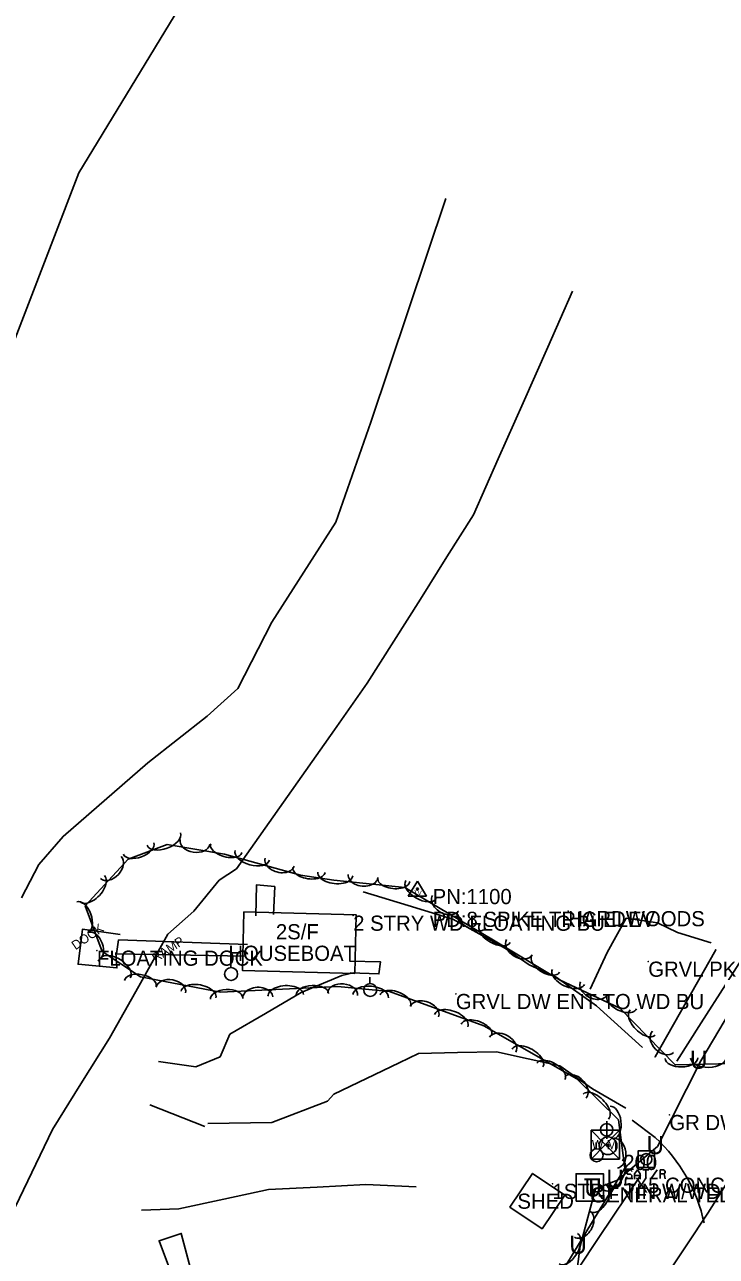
# Model space of a CAD drawing. Extents: x 1451369 to 1458940, y 1868647 to 1875095.
# Drawn here: x 1454865 to 1455092.6, y 1872324.4 to 1872730.1 of the extents above; entities that cross this region are included whole.
import ezdxf

# ---------------------------------------------------------------- set-up
doc = ezdxf.new("R2010")
doc.units = 0
for name, color, linetype in [('Default', 7, 'Continuous'), ('E_Const Align', 7, 'Continuous'), ('E_Const Align Station', 7, 'Continuous'), ('E_Label', 7, 'Continuous'), ('E_Ownership Information', 7, 'Continuous'), ('E_Property Line', 7, 'Continuous'), ('E_Proposed ROW and Easements', 7, 'Continuous'), ('E_Quarter Calls', 7, 'Continuous'), ('E_Quarter Section Line', 7, 'Continuous'), ('E_Row Point', 7, 'Continuous'), ('E_ROW Point Number', 7, 'Continuous'), ('E_Station Offset', 7, 'Continuous'), ('E_Survey Point', 7, 'Continuous'), ('E_Survey Point Number', 7, 'Continuous'), ('E_Title Sheet', 7, 'Continuous'), ('E_Tract Residual', 7, 'Continuous'), ('S_BUILDING_ANNOT', 7, 'Continuous'), ('S_EDGE_PAVEMENT', 7, 'Continuous'), ('S_EXIST_ROW', 7, 'Continuous'), ('S_IRON_PIN_ANNOT', 7, 'Continuous'), ('S_PARKING', 7, 'Continuous'), ('S_SECONDARY_CTL_ANNOT', 7, 'Continuous'), ('S_SIDEWALK', 7, 'Continuous'), ('S_SIDEWALK_ANNOT', 7, 'Continuous'), ('S_SURVEY_TEXT_ANNOT', 7, 'Continuous'), ('S_TELEPHONE_UTILITIES_ANNOT', 7, 'Continuous')]:
    doc.layers.add(name, color=color, linetype=linetype)

msp = doc.modelspace()

# ---------------------------------------------------------------- linework, layer by layer
at = {"layer": 'E_Const Align'}
for p, q in [((1454932.8, 1872419.52), (1454932.8, 1872421.63)), ((1454978.6, 1872414.26), (1454978.6, 1872416.36)), ((1455056.53, 1872363.12), (1455056.53, 1872368.91)), ((1455053.1, 1872359.82), (1455053.1, 1872361.93))]:
    msp.add_line(p, q, dxfattribs=at)
for centre, radius in [((1454932.93, 1872417.38), 2.13), ((1454978.72, 1872412.11), 2.13), ((1455056.53, 1872366.05), 2.05), ((1455053.22, 1872357.68), 2.13)]:
    msp.add_circle(centre, radius, dxfattribs=at)
at = {"layer": 'E_Const Align Station'}
for radius in [2.91, 0.411, 0.262, 0.212, 0.145, 0.0822, 0.0581]:
    msp.add_circle((1455056.98, 1872360.82), radius, dxfattribs=at)
at = {"layer": 'E_Label'}
msp.add_lwpolyline([(1455046.45, 1872342.61), (1455046.45, 1872351.61), (1455055.45, 1872351.61), (1455055.45, 1872342.61)], close=True, dxfattribs=at)
at = {"layer": 'E_Ownership Information'}
for p, q in [((1455062.94, 1872352.38), (1455063.4, 1872352.85)), ((1455062.94, 1872351.84), (1455062.94, 1872352.38)), ((1455063.48, 1872351.45), (1455062.94, 1872351.84)), ((1455063.4, 1872352.85), (1455064.41, 1872352.85)), ((1455064.41, 1872351.45), (1455063.48, 1872351.45)), ((1455064.41, 1872352.85), (1455064.87, 1872352.38)), ((1455064.8, 1872350.99), (1455064.41, 1872351.45)), ((1455065.65, 1872351.61), (1455066.66, 1872352.85)), ((1455065.65, 1872349.82), (1455065.65, 1872351.61)), ((1455066.66, 1872352.85), (1455067.59, 1872351.53)), ((1455067.59, 1872351.53), (1455067.59, 1872349.82)), ((1455068.44, 1872352.85), (1455070.38, 1872352.85)), ((1455069.45, 1872352.85), (1455069.45, 1872349.98)), ((1455071.15, 1872350.06), (1455073.09, 1872352.85)), ((1455074.1, 1872349.98), (1455074.1, 1872352.85)), ((1455074.1, 1872352.85), (1455075.34, 1872352.85)), ((1455075.41, 1872351.61), (1455074.1, 1872351.61)), ((1455075.34, 1872352.85), (1455075.8, 1872352.38)), ((1455075.8, 1872351.99), (1455075.41, 1872351.61)), ((1455075.41, 1872351.61), (1455075.8, 1872349.9)), ((1455075.8, 1872352.38), (1455075.8, 1872351.99)), ((1455062.94, 1872350.6), (1455063.4, 1872349.98)), ((1455063.4, 1872349.98), (1455064.33, 1872349.98)), ((1455064.33, 1872349.98), (1455064.8, 1872350.52)), ((1455064.8, 1872350.52), (1455064.8, 1872350.99)), ((1455067.51, 1872350.99), (1455065.65, 1872350.99))]:
    msp.add_line(p, q, dxfattribs=at)
msp.add_lwpolyline([(1455066.89, 1872353.6), (1455066.89, 1872359.1), (1455072.23, 1872359.1), (1455072.23, 1872353.6)], close=True, dxfattribs=at)
msp.add_circle((1455069.55, 1872356.37), 1.86, dxfattribs=at)
at = {"layer": 'E_Property Line'}
for p, q in [((1454916.52, 1872331.87), (1454909.24, 1872329.5)), ((1454919.62, 1872320.41), (1454916.52, 1872331.87)), ((1454909.24, 1872329.5), (1454912.94, 1872319.5))]:
    msp.add_line(p, q, dxfattribs=at)
for points in [[(1454937.15, 1872437.84), (1454974.14, 1872436.85), (1454973.62, 1872417.59), (1454936.63, 1872418.58)], [(1455042.74, 1872344.58), (1455035.26, 1872333.46), (1455024.66, 1872340.59), (1455032.15, 1872351.71)]]:
    msp.add_lwpolyline(points, close=True, dxfattribs=at)
at = {"layer": 'E_Proposed ROW and Easements'}
for points in [[(1455043.87, 1872438.11), (1455043.87, 1872438.16), (1455043.87, 1872438.11), (1455043.82, 1872438.11), (1455043.87, 1872438.11), (1455043.87, 1872438.06), (1455043.87, 1872438.11), (1455043.92, 1872438.11)], [(1454888.77, 1872425.11), (1454888.77, 1872425.16), (1454888.77, 1872425.11), (1454888.72, 1872425.11), (1454888.77, 1872425.11), (1454888.77, 1872425.06), (1454888.77, 1872425.11), (1454888.82, 1872425.11)], [(1455092.45, 1872425.31), (1455092.45, 1872425.36), (1455092.45, 1872425.31), (1455092.4, 1872425.31), (1455092.45, 1872425.31), (1455092.45, 1872425.26), (1455092.45, 1872425.31), (1455092.5, 1872425.31)], [(1455070.2, 1872421.47), (1455070.2, 1872421.52), (1455070.2, 1872421.47), (1455070.15, 1872421.47), (1455070.2, 1872421.47), (1455070.2, 1872421.42), (1455070.2, 1872421.47), (1455070.25, 1872421.47)], [(1455006.89, 1872410.82), (1455006.89, 1872410.87), (1455006.89, 1872410.82), (1455006.84, 1872410.82), (1455006.89, 1872410.82), (1455006.89, 1872410.77), (1455006.89, 1872410.82), (1455006.94, 1872410.82)], [(1455072.47, 1872390.08), (1455072.47, 1872390.13), (1455072.47, 1872390.08), (1455072.42, 1872390.08), (1455072.47, 1872390.08), (1455072.47, 1872390.03), (1455072.47, 1872390.08), (1455072.52, 1872390.08)], [(1455077.15, 1872370.96), (1455077.15, 1872371.01), (1455077.15, 1872370.96), (1455077.1, 1872370.96), (1455077.15, 1872370.96), (1455077.15, 1872370.91), (1455077.15, 1872370.96), (1455077.2, 1872370.96)]]:
    msp.add_lwpolyline(points, dxfattribs=at)
at = {"layer": 'E_Quarter Calls'}
for points in [[(1454976.44, 1872444.51), (1454991.15, 1872439.99), (1455005.87, 1872435.46), (1455023.24, 1872425.74), (1455031.05, 1872420.37), (1455039.88, 1872416.36), (1455053.2, 1872406.86), (1455068.31, 1872393.21)], [(1454973.11, 1872417.74), (1454969.32, 1872416.9), (1454955.98, 1872411.28), (1454944.26, 1872404.41), (1454932.54, 1872397.53), (1454929.29, 1872390.13), (1454921.35, 1872386.85), (1454909.01, 1872388.53)], [(1455062.84, 1872373.24), (1455051.87, 1872379.58), (1455041.12, 1872387.12), (1455020.27, 1872391.79), (1455007.41, 1872391.49), (1454994.56, 1872391.19), (1454988.25, 1872388.16), (1454966.79, 1872377.84), (1454964.68, 1872375.49), (1454946.32, 1872368.43), (1454925.28, 1872368.11)], [(1454906.2, 1872374.25), (1454924.25, 1872367.19)]]:
    msp.add_lwpolyline(points, dxfattribs=at)
at = {"layer": 'E_Quarter Section Line'}
for p, q in [((1455051.44, 1872365.91), (1455060.78, 1872365.91)), ((1455051.44, 1872365.91), (1455051.44, 1872356.42)), ((1455051.44, 1872365.91), (1455060.78, 1872356.42)), ((1455060.78, 1872365.91), (1455051.44, 1872356.42)), ((1455060.78, 1872365.91), (1455060.78, 1872356.42)), ((1455051.44, 1872356.42), (1455060.78, 1872356.42))]:
    msp.add_line(p, q, dxfattribs=at)
at = {"layer": 'E_Row Point'}
for points in [[(1454973.1, 1872436.63), (1454973.1, 1872436.68), (1454973.1, 1872436.63), (1454973.05, 1872436.63), (1454973.1, 1872436.63), (1454973.1, 1872436.58), (1454973.1, 1872436.63), (1454973.15, 1872436.63)], [(1455038.7, 1872348.28), (1455038.7, 1872348.33), (1455038.7, 1872348.28), (1455038.65, 1872348.28), (1455038.7, 1872348.28), (1455038.7, 1872348.23), (1455038.7, 1872348.28), (1455038.75, 1872348.28)], [(1454916.52, 1872331.87), (1454916.52, 1872331.92), (1454916.52, 1872331.87), (1454916.47, 1872331.87), (1454916.52, 1872331.87), (1454916.52, 1872331.82), (1454916.52, 1872331.87), (1454916.57, 1872331.87)], [(1454909.24, 1872329.5), (1454909.24, 1872329.55), (1454909.24, 1872329.5), (1454909.19, 1872329.5), (1454909.24, 1872329.5), (1454909.24, 1872329.45), (1454909.24, 1872329.5), (1454909.29, 1872329.5)]]:
    msp.add_lwpolyline(points, dxfattribs=at)
at = {"layer": 'E_ROW Point Number'}
msp.add_lwpolyline([(1455098.05, 1872387.88), (1455079.09, 1872387.5), (1455060.84, 1872406.11), (1455040.95, 1872415.5), (1455019.23, 1872428.58), (1454990.11, 1872445.89), (1454966.75, 1872448.29), (1454955.74, 1872449.91), (1454930.75, 1872456.82), (1454911.92, 1872460), (1454899.09, 1872455.18), (1454884.95, 1872439.86), (1454890.45, 1872424.8), (1454903.13, 1872416.45), (1454929.48, 1872411.4), (1454968, 1872413.3), (1454985.09, 1872411.68), (1455016.13, 1872400.35), (1455046.73, 1872382.86), (1455060.4, 1872369.3), (1455062.48, 1872353.46), (1455043.07, 1872321.41)], dxfattribs=at)
for centre, major_axis, ratio, start_param, end_param in [((1454910.78, 1872461.84), (5.49, 2.06), 0.550069, 3.141593, 6.283185), ((1454921.03, 1872460.88), (4.89, -0.82), 0.685316, 3.141602, 6.283194), ((1454902.48, 1872458.72), (5, 1.88), 0.540689, 3.141593, 6.283185), ((1454931.36, 1872458.86), (5.15, -1.43), 0.540756, 3.141628, 6.283221), ((1454939.91, 1872456.49), (5.66, -1.56), 0.550137, 3.14163, 6.283222), ((1454893.35, 1872452.47), (3.36, 3.64), 0.685264, 3.141626, 6.283218), ((1454948.9, 1872454.27), (4.78, -1.32), 0.685382, 3.141653, 6.283246), ((1454887.26, 1872445.49), (3.98, 4.31), 0.550042, 3.141613, 6.283206), ((1454958.56, 1872451.64), (5.28, -0.78), 0.541158, 3.141633, 6.283226), ((1454967.23, 1872450.37), (5.77, -0.59), 0.556922, 3.141671, 6.283264), ((1454976.36, 1872449.7), (4.87, -0.5), 0.693835, 3.141723, 6.283316), ((1454986.45, 1872448.4), (5.25, -0.54), 0.547425, 3.141669, 6.283262), ((1454995.41, 1872445.21), (5.02, -2.99), 0.552475, 3.142113, 6.283705), ((1454884.04, 1872436.16), (-1.84, 5.02), 0.540646, 3.141593, 6.283185), ((1455003.47, 1872440.72), (4.24, -2.52), 0.688294, 3.142448, 6.284041), ((1455012.15, 1872435.26), (4.57, -2.72), 0.543054, 3.142096, 6.283689), ((1455019.74, 1872430.74), (5.02, -2.99), 0.552475, 3.142113, 6.283705), ((1454887.33, 1872426.4), (-1.7, 4.65), 0.685243, 3.141593, 6.283185), ((1455027.79, 1872426.21), (4.23, -2.55), 0.687824, 3.142385, 6.283977), ((1454894.87, 1872419.35), (-4.89, 3.23), 0.550672, 3.141876, 6.283468), ((1455036.45, 1872420.69), (4.56, -2.75), 0.542682, 3.142059, 6.283652), ((1454903.08, 1872414.3), (-5.23, 1), 0.542992, 3.141731, 6.283323), ((1455043.93, 1872416.44), (5.28, -2.49), 0.553213, 3.142075, 6.283668), ((1454913.11, 1872412.11), (-4.85, 0.93), 0.688216, 3.141827, 6.283419), ((1454922.21, 1872410.63), (-5.74, 1.1), 0.552412, 3.141735, 6.283328), ((1454931.42, 1872409.37), (-5.32, -0.26), 0.542588, 3.141484, 6.283076), ((1454941.69, 1872409.61), (-4.93, -0.24), 0.687705, 3.141408, 6.283001), ((1454950.89, 1872410.33), (-5.84, -0.29), 0.552001, 3.14148, 6.283073), ((1454959.71, 1872410.76), (-5.32, -0.26), 0.542588, 3.141484, 6.283076), ((1454969.64, 1872410.75), (-4.92, 0.46), 0.686711, 3.141634, 6.283226), ((1454978.86, 1872410.14), (-5.83, 0.55), 0.551204, 3.141618, 6.28321), ((1454986.99, 1872408.73), (-5.02, 1.83), 0.540945, 3.141694, 6.283287), ((1455052.37, 1872412.75), (4.45, -2.11), 0.689214, 3.142387, 6.28398), ((1454996.57, 1872404.95), (-4.65, 1.7), 0.685623, 3.141764, 6.283357), ((1455061.52, 1872408.14), (4.81, -2.27), 0.543779, 3.14206, 6.283653), ((1455005.35, 1872402.03), (-5.51, 2.01), 0.55033, 3.141697, 6.28329), ((1455068.39, 1872401.45), (4.11, -4.19), 0.550148, 3.141744, 6.283337), ((1455013.68, 1872398.99), (-5.02, 1.83), 0.540945, 3.141694, 6.283287), ((1455022.3, 1872394.08), (-4.3, 2.46), 0.685433, 3.141768, 6.28336), ((1455075.06, 1872395.02), (3.47, -3.54), 0.685395, 3.141841, 6.283433), ((1455030.47, 1872389.71), (-5.09, 2.91), 0.550178, 3.141699, 6.283292), ((1455038.16, 1872385.32), (-4.64, 2.65), 0.540796, 3.141696, 6.283289), ((1455081.16, 1872389.67), (5.35, 0.11), 0.540706, 3.141588, 6.28318), ((1455090.02, 1872389.84), (5.87, 0.12), 0.550087, 3.141588, 6.28318), ((1455046.22, 1872380.02), (-3.51, 3.49), 0.686374, 3.142333, 6.283926), ((1455052.96, 1872373.69), (-4.16, 4.13), 0.550933, 3.142044, 6.283637), ((1455058.36, 1872368.54), (-0.69, 5.27), 0.544279, 3.142942, 6.284534), ((1455059.44, 1872358.36), (-0.64, 4.88), 0.689847, 3.143889, 6.285481), ((1455058.62, 1872351.17), (3.04, 5.01), 0.55061, 3.142085, 6.283677), ((1455054.03, 1872343.6), (2.77, 4.57), 0.54122, 3.142069, 6.283662), ((1455048.47, 1872334.93), (2.57, 4.23), 0.685971, 3.142399, 6.283992), ((1455043.9, 1872326.88), (3.04, 5.01), 0.55061, 3.142085, 6.283677)]:
    msp.add_ellipse(centre, major_axis=major_axis, ratio=ratio, start_param=start_param, end_param=end_param, dxfattribs=at)
at = {"layer": 'E_Station Offset'}
for p, q in [((1454994.25, 1872448.01), (1454991.24, 1872443.06)), ((1454994.25, 1872448.01), (1454997.19, 1872443.06)), ((1454991.24, 1872443.06), (1454997.19, 1872443.06))]:
    msp.add_line(p, q, dxfattribs=at)
for radius in [0.311, 0.183, 0.103]:
    msp.add_circle((1454994.25, 1872445.4), radius, dxfattribs=at)
at = {"layer": 'E_Survey Point'}
msp.add_line((1455092.45, 1872425.31), (1455072.47, 1872390.08), dxfattribs=at)
at = {"layer": 'E_Survey Point Number'}
for p, q in [((1455099.32, 1872408.78), (1455087.55, 1872388.74)), ((1455087.55, 1872388.74), (1455073.23, 1872360.57)), ((1455073.23, 1872360.57), (1455060.04, 1872349.5)), ((1455060.04, 1872349.5), (1455052.8, 1872346.64)), ((1455052.8, 1872346.64), (1455047.85, 1872327.75)), ((1455047.85, 1872327.75), (1455045.4, 1872309.63))]:
    msp.add_line(p, q, dxfattribs=at)
at = {"layer": 'E_Title Sheet'}
msp.add_line((1455069.55, 1872356.37), (1455069.55, 1872356.37), dxfattribs=at)
at = {"layer": 'E_Tract Residual'}
for points in [[(1454915.78, 1872735.4), (1454882.85, 1872681.3), (1454846.79, 1872587.87)], [(1455003.6, 1872672.86), (1454978.94, 1872599.14), (1454967.41, 1872566.25), (1454946.29, 1872533.26), (1454935.11, 1872511.43), (1454925.1, 1872502.35), (1454905.58, 1872486.92), (1454877.64, 1872462.73), (1454869.64, 1872453.51), (1454863.9, 1872442.52)], [(1455045.26, 1872642.33), (1455037.13, 1872623.91), (1455029, 1872605.5), (1455020.86, 1872587.09), (1455012.73, 1872568.68), (1455003.98, 1872554.79), (1454995.24, 1872540.91), (1454986.49, 1872527.02), (1454977.74, 1872513.14), (1454966.99, 1872497.86), (1454956.23, 1872482.59), (1454945.47, 1872467.32), (1454934.71, 1872452.05), (1454928.99, 1872448.26), (1454920.71, 1872438.13), (1454912.14, 1872430.46), (1454902.52, 1872413.38), (1454892.89, 1872396.29), (1454883.53, 1872381.23), (1454874.16, 1872366.17), (1454867.36, 1872352.01), (1454860.57, 1872337.84)]]:
    msp.add_lwpolyline(points, dxfattribs=at)
at = {"layer": 'S_EDGE_PAVEMENT'}
msp.add_lwpolyline([(1455213.17, 1872599.83), (1455206.82, 1872580.17), (1455200.46, 1872560.51), (1455191.43, 1872537.24), (1455182.4, 1872513.97), (1455172.69, 1872491.36), (1455162.99, 1872468.75), (1455157.08, 1872456.69), (1455151.17, 1872444.64), (1455145.25, 1872432.58), (1455139.34, 1872420.52), (1455126.92, 1872399.17), (1455114.51, 1872377.81), (1455102.18, 1872358.23), (1455089.86, 1872338.64), (1455082.86, 1872328.15), (1455075.85, 1872317.66)], dxfattribs=at)
at = {"layer": 'S_EXIST_ROW'}
for points in [[(1455190.29, 1872610.09), (1455184.14, 1872590.23), (1455178, 1872570.37), (1455172.83, 1872558.64), (1455167.67, 1872546.91), (1455162.5, 1872535.18), (1455157.33, 1872523.45), (1455145.25, 1872502.49), (1455133.16, 1872481.53), (1455122.44, 1872460.28), (1455111.71, 1872439.03), (1455103.69, 1872426.44), (1455095.67, 1872413.86), (1455087.65, 1872401.27), (1455079.63, 1872388.69)], [(1455067.63, 1872351.06), (1455053.98, 1872330.57), (1455040.32, 1872310.08), (1455028.09, 1872291.25), (1455015.85, 1872272.42), (1455003.61, 1872253.59), (1454991.38, 1872234.76), (1454982.74, 1872224.5), (1454974.11, 1872214.23), (1454965.48, 1872203.97), (1454956.84, 1872193.71), (1454945.77, 1872171.92), (1454934.69, 1872150.13), (1454927.44, 1872139.88), (1454920.2, 1872129.63), (1454912.95, 1872119.39), (1454905.71, 1872109.14), (1454898.46, 1872098.89), (1454891.21, 1872088.65), (1454883.97, 1872078.4), (1454876.72, 1872068.15), (1454867.48, 1872058.62), (1454858.23, 1872049.09)], [(1454993.79, 1872347.27), (1454977.26, 1872348.04), (1454961.26, 1872347.21), (1454945.26, 1872346.38), (1454930.51, 1872343.22), (1454915.77, 1872340.06), (1454903.43, 1872339.55)]]:
    msp.add_lwpolyline(points, dxfattribs=at)
at = {"layer": 'S_PARKING'}
for points in [[(1455090.87, 1872427.65), (1455079.82, 1872431.08), (1455073.25, 1872434.28), (1455062.9, 1872435.74), (1455056.66, 1872424.45), (1455051.07, 1872412.35)], [(1455072.52, 1872363.53), (1455064.96, 1872369.29)]]:
    msp.add_lwpolyline(points, dxfattribs=at)
msp.add_ellipse((1455043.31, 1872330.5), major_axis=(-32.08, 37.6), ratio=0.8905, start_param=4.166598, end_param=4.837602, dxfattribs=at)
at = {"layer": 'S_SIDEWALK'}
for points in [[(1454946.93, 1872436.98), (1454947.3, 1872446.18), (1454941.32, 1872446.78), (1454941.04, 1872436.55)], [(1454896.38, 1872430.44), (1454884.07, 1872432.16), (1454882.59, 1872420.58), (1454895.34, 1872419.38), (1454895.04, 1872424.49)], [(1454937.75, 1872423.32), (1454895.18, 1872424.04), (1454895.89, 1872428.6), (1454938.38, 1872427.08)], [(1454971.89, 1872421.62), (1454982.1, 1872421.39), (1454981.56, 1872417.42), (1454972.12, 1872417.77)]]:
    msp.add_lwpolyline(points, dxfattribs=at)

# ---------------------------------------------------------------- texts
at = {"layer": 'Default'}
for p in [(1455083.92, 1872386.19), (1455069.6, 1872358.02), (1455056.41, 1872346.95), (1455049.17, 1872344.09), (1455044.22, 1872325.21)]:
    msp.add_text('U', height=6, rotation=360, dxfattribs=at).set_placement(p)
at = {"layer": 'E_Label'}
msp.add_text('T', height=6, rotation=360, dxfattribs=at).set_placement((1455049.01, 1872344.11))
at = {"layer": 'E_Quarter Section Line'}
msp.add_text('W M', height=3, rotation=360, dxfattribs=at).set_placement((1455051.64, 1872359.68))
at = {"layer": 'E_Station Offset'}
msp.add_text('TV', height=1.5, rotation=360, dxfattribs=at).set_placement((1454993.04, 1872443.39))
at = {"layer": 'S_BUILDING_ANNOT'}
for s, height, p in [('2 STRY WD FLOATING BU', 5, (1454973.1, 1872431.63)), ('2S/F', 5.001, (1454947.67, 1872428.81)), ('HOUSEBOAT', 5.001, (1454932.04, 1872421.72)), ('1STRY TIN W/WD ROOF DELAPIDATED', 5, (1455038.7, 1872343.28)), ('SHED', 5.001, (1455027.16, 1872340.05))]:
    msp.add_text(s, height=height, dxfattribs=at).set_placement(p)
at = {"layer": 'S_IRON_PIN_ANNOT'}
for s, p in [('200', (1455061.98, 1872352.82)), ('5X5 CONC MRW DIST', (1455061.98, 1872345.32))]:
    msp.add_text(s, height=5, dxfattribs=at).set_placement(p)
at = {"layer": 'S_SECONDARY_CTL_ANNOT'}
for s, p in [('PN:1100', (1454999.25, 1872440.4)), ('PD:8 SPIKE TRIG ELEV', (1454999.25, 1872432.9))]:
    msp.add_text(s, height=5, dxfattribs=at).set_placement(p)
at = {"layer": 'S_SIDEWALK_ANNOT'}
for s, rotation, p in [('DOCK', 34.3129, (1454881.72, 1872425.19)), ('RAMP', 33.2598, (1454908.1, 1872421.09))]:
    msp.add_text(s, height=3, rotation=rotation, dxfattribs=at).set_placement(p)
at = {"layer": 'S_SURVEY_TEXT_ANNOT'}
for s, p in [('HARDWOODS', (1455043.87, 1872433.11)), ('FLOATING DOCK', (1454888.77, 1872420.11)), ('GRVL PK', (1455070.2, 1872416.47)), ('GRVL DW ENT TO WD BU', (1455006.89, 1872405.82)), ('GR DW ENT TO FLOATING BU NO CUS', (1455077.15, 1872365.96))]:
    msp.add_text(s, height=5, dxfattribs=at).set_placement(p)
at = {"layer": 'S_TELEPHONE_UTILITIES_ANNOT'}
msp.add_text('GENERAL TELPHONE CO', height=5, dxfattribs=at).set_placement((1455051.18, 1872342.13))

doc.saveas('drawing.dxf')
